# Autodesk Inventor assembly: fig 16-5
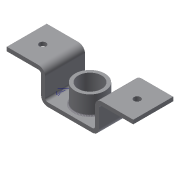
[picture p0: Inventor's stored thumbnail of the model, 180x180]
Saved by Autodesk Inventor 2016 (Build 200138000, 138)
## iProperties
Created: 2004-07
Part Number: fig 16-5
Document SubType Name: Weldment
Designer: CADCIM Technologies
Manufacturer: Standard
Standards Organization: Custom
Author: CADCIM Technologies
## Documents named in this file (3)
- D:\KAVITA\Autodesk Inventor_ 2016 Project_Kavita\Inventor_Part Files\Inventor_2016_Part\c16_Inv_2016\c16_inv_2016_prt\fig 16-5\fig 16-5.iam
- D:\KAVITA\Autodesk Inventor_ 2016 Project_Kavita\Inventor_Part Files\Inventor_2016_Part\c16_Inv_2016\c16_inv_2016_prt\fig 16-5\Bracket.ipt
- D:\KAVITA\Autodesk Inventor_ 2016 Project_Kavita\Inventor_Part Files\Inventor_2016_Part\c16_Inv_2016\c16_inv_2016_prt\fig 16-5\cylinder.ipt
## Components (2 placed, 2 different names)
1. Bracket:1 — Insert:1
2. cylinder:1 — Insert:1
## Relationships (1: Insert 1)
- Insert:1: Bracket:1 ↔ cylinder:1
